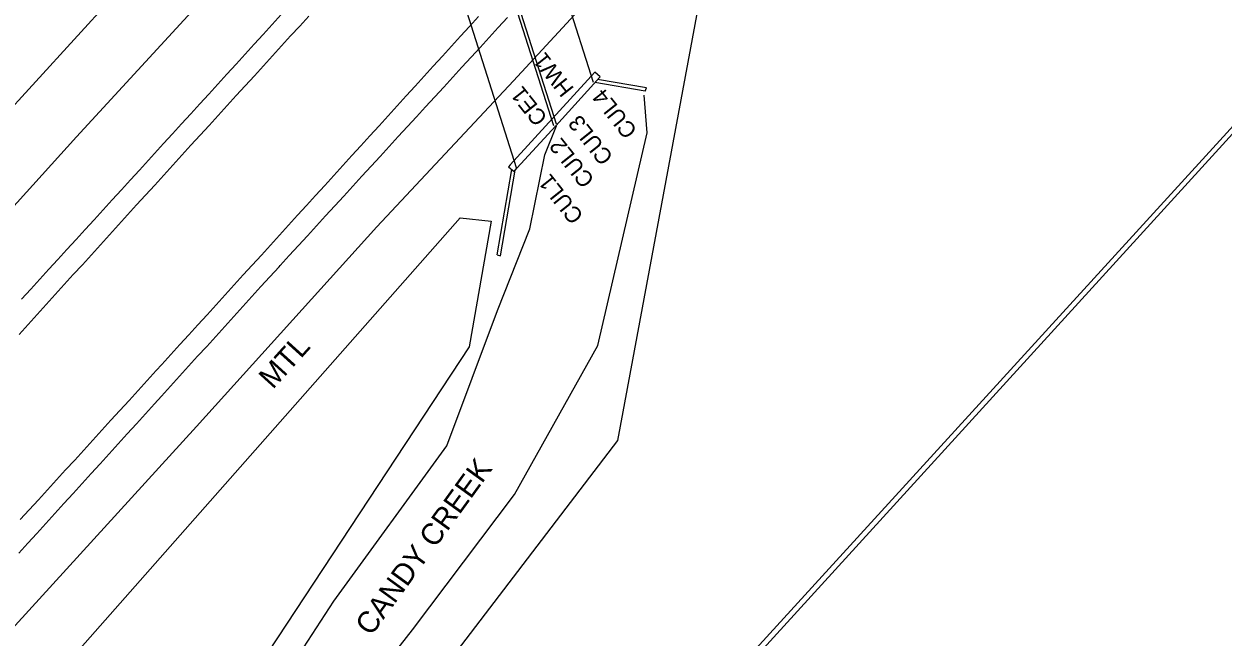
# Model space of a CAD drawing. Extents: x 1806071 to 1809844, y 912722 to 917035.
# Drawn here: x 1808478 to 1808701, y 915262.3 to 915376.2 of the extents above; entities that cross this region are included whole.
import ezdxf

# ---------------------------------------------------------------- set-up
doc = ezdxf.new("R2010")
doc.units = 0
for name, color, linetype in [('Exist Guardrail', 7, 'Continuous'), ('Exist Guardrail Cable Guide Rail', 7, 'Continuous'), ('Exist Guardrail Text', 7, 'Continuous'), ('Exist Horizontal Alignment', 7, 'Continuous'), ('Exist Hydro Stream or Body of Water', 7, 'Continuous'), ('Exist Hydro Stream or Body of Water Text', 7, 'Continuous'), ('Exist Other Culture Fence Line', 7, 'Continuous'), ('Exist Right of Way Line', 7, 'Continuous'), ('Exist Roads EOP', 7, 'Continuous'), ('Exist Roads EOT', 7, 'Continuous'), ('Exist Structure Major Box Culvert or Tunnel Topo', 7, 'Continuous'), ('Exist Structure Major Bridge WW', 7, 'Continuous'), ('Exist Structure Major Deck Tunnel Box Culvert Text', 7, 'Continuous'), ('Exist Structure Minor Head and End Wall', 7, 'Continuous'), ('Exist Vegetation Woods Line', 7, 'Continuous')]:
    doc.layers.add(name, color=color, linetype=linetype)

msp = doc.modelspace()

# ---------------------------------------------------------------- linework, layer by layer
at = {"layer": 'Exist Guardrail'}
msp.add_lwpolyline([(1808591.05, 915389.5), (1808569.06, 915365.7), (1808543.65, 915338.5), (1808510.12, 915301.43), (1808476.4, 915264.39), (1808442.71, 915227.63), (1808412.8, 915194.83), (1808379.91, 915158.29), (1808346.06, 915121.3), (1808316.39, 915089.09), (1808287.07, 915056.31), (1808258.76, 915023.41), (1808230.12, 914989.62), (1808202.58, 914956.19), (1808174.39, 914923.17), (1808146.14, 914889.53), (1808117.77, 914855.87), (1808088.77, 914822.19), (1808060.62, 914790.15), (1808030.71, 914757.47), (1808001.37, 914724.91), (1807974.55, 914694.38)], dxfattribs=at)
at = {"layer": 'Exist Guardrail Cable Guide Rail'}
msp.add_lwpolyline([(1808336.06, 915188.72), (1808363.24, 915218.4), (1808387.13, 915244.72), (1808412.78, 915272.78), (1808437.24, 915299.61), (1808463.92, 915328.91), (1808487.83, 915355.26), (1808513.5, 915383.23), (1808538.93, 915411.52), (1808563.03, 915437.7), (1808575.67, 915451.68), (1808586.31, 915463.32), (1808592.39, 915469.88), (1808616.15, 915495.99), (1808637.91, 915519.85), (1808660.97, 915545.25), (1808684.67, 915571.48), (1808707.85, 915596.81)], dxfattribs=at)
at = {"layer": 'Exist Horizontal Alignment'}
msp.add_line((1806073.69, 912724.84), (1809374.2, 916346.52), dxfattribs=at)
at = {"layer": 'Exist Hydro Stream or Body of Water'}
for points in [[(1808520.56, 915222.15), (1808528.5, 915235.71), (1808550.31, 915263.62), (1808569.28, 915288.78), (1808584.74, 915316.49), (1808593.9, 915355.98), (1808593.37, 915362.99)], [(1808535.69, 915268.92), (1808556.66, 915297.83), (1808566.08, 915322.96), (1808572.13, 915338.17), (1808574.92, 915351.92), (1808577.05, 915357.31)], [(1808507.82, 915230.69), (1808517.93, 915241.7), (1808535.69, 915268.92)]]:
    msp.add_lwpolyline(points, dxfattribs=at)
at = {"layer": 'Exist Other Culture Fence Line'}
msp.add_lwpolyline([(1809083.03, 915774.32), (1808984.81, 915666.52), (1808925.72, 915601.39), (1808852.14, 915520.8), (1808595.36, 915239.5)], dxfattribs=at)
at = {"layer": 'Exist Right of Way Line'}
msp.add_line((1809840.95, 916604.82), (1808525.76, 915161.65), dxfattribs=at)
at = {"layer": 'Exist Roads EOP'}
for points in [[(1808477.08, 915277.85), (1808478.76, 915279.7), (1808480.44, 915281.55), (1808482.12, 915283.4), (1808483.8, 915285.25), (1808485.48, 915287.1), (1808487.17, 915288.95), (1808488.85, 915290.8), (1808490.53, 915292.65), (1808492.21, 915294.5), (1808493.89, 915296.35), (1808495.57, 915298.2), (1808497.25, 915300.05), (1808498.94, 915301.9), (1808500.62, 915303.75), (1808502.3, 915305.6), (1808503.62, 915307.05), (1808505.3, 915308.9), (1808506.98, 915310.76), (1808508.66, 915312.61), (1808510.34, 915314.46), (1808512.02, 915316.31), (1808513.7, 915318.16), (1808515.38, 915320.01), (1808517.06, 915321.86), (1808518.75, 915323.71), (1808520.43, 915325.56), (1808522.11, 915327.41), (1808523.79, 915329.26), (1808525.47, 915331.12), (1808525.68, 915331.35), (1808527.37, 915333.2), (1808529.06, 915335.04), (1808530.75, 915336.88), (1808532.44, 915338.72), (1808534.13, 915340.57), (1808535.82, 915342.41), (1808537.51, 915344.25), (1808539.2, 915346.09), (1808540.89, 915347.94), (1808542.58, 915349.78), (1808544.27, 915351.62), (1808545.96, 915353.46), (1808547.65, 915355.31), (1808549.34, 915357.15), (1808551.03, 915358.99), (1808552.72, 915360.83), (1808554.41, 915362.68), (1808556.1, 915364.52), (1808557.79, 915366.36), (1808559.48, 915368.2), (1808561.17, 915370.05), (1808562.86, 915371.89), (1808564.55, 915373.73), (1808566.24, 915375.57), (1808567.93, 915377.42)], [(1808525.89, 915378), (1808524.21, 915376.16), (1808522.52, 915374.31), (1808520.84, 915372.46), (1808519.15, 915370.61), (1808517.47, 915368.77), (1808515.79, 915366.92), (1808514.1, 915365.07), (1808512.42, 915363.22), (1808510.73, 915361.38), (1808509.05, 915359.53), (1808507.36, 915357.68), (1808505.68, 915355.83), (1808504, 915353.99), (1808502.31, 915352.14), (1808501.22, 915350.94), (1808499.53, 915349.09), (1808497.84, 915347.25), (1808496.16, 915345.4), (1808494.47, 915343.56), (1808492.78, 915341.71), (1808491.1, 915339.86), (1808489.41, 915338.02), (1808487.72, 915336.17), (1808486.04, 915334.33), (1808484.35, 915332.48), (1808482.66, 915330.64), (1808480.98, 915328.79), (1808479.29, 915326.95), (1808477.6, 915325.1)]]:
    msp.add_lwpolyline(points, dxfattribs=at)
at = {"layer": 'Exist Roads EOT'}
for points in [[(1808530.99, 915377.7), (1808529.31, 915375.86), (1808527.62, 915374.01), (1808525.94, 915372.16), (1808524.25, 915370.31), (1808522.57, 915368.47), (1808520.88, 915366.62), (1808519.2, 915364.77), (1808517.51, 915362.93), (1808515.83, 915361.08), (1808514.15, 915359.23), (1808512.46, 915357.38), (1808510.78, 915355.54), (1808509.09, 915353.69), (1808507.41, 915351.84), (1808505.72, 915349.99), (1808504.04, 915348.15), (1808502.35, 915346.3), (1808500.66, 915344.44), (1808498.98, 915342.59), (1808497.3, 915340.74), (1808495.62, 915338.89), (1808493.94, 915337.04), (1808492.26, 915335.19), (1808490.58, 915333.34), (1808488.9, 915331.49), (1808487.22, 915329.64), (1808485.54, 915327.79), (1808483.86, 915325.93), (1808482.18, 915324.08), (1808480.5, 915322.23), (1808478.82, 915320.38), (1808477.14, 915318.53)], [(1808477.35, 915284.1), (1808479.04, 915285.95), (1808480.72, 915287.8), (1808482.41, 915289.64), (1808484.1, 915291.49), (1808485.78, 915293.34), (1808487.47, 915295.18), (1808489.15, 915297.03), (1808490.84, 915298.88), (1808492.52, 915300.72), (1808494.21, 915302.57), (1808495.89, 915304.41), (1808497.58, 915306.26), (1808499.26, 915308.11), (1808500.95, 915309.95), (1808502.63, 915311.8), (1808503.67, 915312.94), (1808505.35, 915314.79), (1808507.04, 915316.63), (1808508.72, 915318.48), (1808510.4, 915320.33), (1808512.09, 915322.18), (1808513.77, 915324.03), (1808515.45, 915325.88), (1808517.13, 915327.73), (1808518.82, 915329.58), (1808520.5, 915331.42), (1808522.18, 915333.27), (1808523.87, 915335.12), (1808525.55, 915336.97), (1808527.23, 915338.82), (1808528.92, 915340.67), (1808530.6, 915342.52), (1808532.28, 915344.37), (1808533.96, 915346.22), (1808535.65, 915348.06), (1808537.33, 915349.91), (1808539.01, 915351.76), (1808540.7, 915353.61), (1808542.38, 915355.46), (1808544.06, 915357.31), (1808545.74, 915359.16), (1808547.43, 915361.01), (1808549.11, 915362.85), (1808550.79, 915364.7), (1808552.48, 915366.55), (1808554.16, 915368.4), (1808555.84, 915370.25), (1808557.52, 915372.1), (1808559.21, 915373.95), (1808560.89, 915375.8), (1808562.57, 915377.64)]]:
    msp.add_lwpolyline(points, dxfattribs=at)
at = {"layer": 'Exist Structure Major Box Culvert or Tunnel Topo'}
for p, q in [((1808583.97, 915365.39), (1808519.67, 915567.57)), ((1808512.7, 915559.72), (1808576.98, 915357.67)), ((1808576.55, 915357.32), (1808512.26, 915559.39)), ((1808505.3, 915551.64), (1808569.58, 915349.53))]:
    msp.add_line(p, q, dxfattribs=at)
at = {"layer": 'Exist Structure Major Bridge WW'}
for p, q in [((1808593.58, 915363.74), (1808593.77, 915364.36)), ((1808566.02, 915333.35), (1808566.65, 915333.13))]:
    msp.add_line(p, q, dxfattribs=at)
at = {"layer": 'Exist Structure Minor Head and End Wall'}
for p, q in [((1808593.77, 915364.36), (1808584.71, 915365.92)), ((1808593.58, 915363.74), (1808584.21, 915365.37)), ((1808566.02, 915333.35), (1808568.74, 915349.17)), ((1808566.65, 915333.13), (1808569.4, 915349.05)), ((1808568.14, 915349.7), (1808569.18, 915348.79))]:
    msp.add_line(p, q, dxfattribs=at)
for points in [[(1808576.91, 915357.33), (1808585.16, 915366.41), (1808584.22, 915367.31), (1808568.47, 915350.04), (1808568.14, 915349.7)], [(1808569.18, 915348.79), (1808569.7, 915349.44), (1808576.91, 915357.33)]]:
    msp.add_lwpolyline(points, dxfattribs=at)
at = {"layer": 'Exist Vegetation Woods Line'}
for points in [[(1808397.76, 915010.37), (1808398.17, 915063.08), (1808401.78, 915078.95), (1808456.47, 915136.33), (1808525.87, 915216.84), (1808588.47, 915298.84), (1808603.34, 915378.8), (1808593.62, 915389.17), (1808703.69, 915510.62), (1809133.9, 915968.11), (1809176.35, 915989.33), (1809248.65, 915971.39)], [(1808108.12, 914683.23), (1808099.27, 914714.87), (1808116.08, 914804.21), (1808120.23, 914842.94), (1808559.12, 915340.21), (1808564.92, 915339.58), (1808560.84, 915316.2), (1808513.2, 915243.98), (1808463.81, 915181.71), (1808444.02, 915172.44), (1808388.95, 915106.15), (1808359.09, 915070.98), (1808353.92, 915054.91), (1808362.94, 915036.53), (1808366.74, 915015.13), (1808346.47, 914993.89), (1808341.37, 914946.67)]]:
    msp.add_lwpolyline(points, dxfattribs=at)

# ---------------------------------------------------------------- texts
at = {"layer": 'Exist Guardrail Text'}
msp.add_text('MTL', height=4, rotation=47.8718, dxfattribs=at).set_placement((1808524.32, 915308.19))
at = {"layer": 'Exist Hydro Stream or Body of Water Text'}
msp.add_text('CANDY CREEK', height=4, rotation=54.0436, dxfattribs=at).set_placement((1808542.59, 915262.29))
at = {"layer": 'Exist Structure Major Deck Tunnel Box Culvert Text'}
for s, p in [('HW1', (1808580.44, 915364.23)), ('CE1', (1808575.54, 915358.81)), ('CUL4', (1808592.22, 915356.45)), ('CUL3', (1808587.76, 915351.54)), ('CUL2', (1808584.27, 915347.3)), ('CUL1', (1808582.24, 915340.58))]:
    msp.add_text(s, height=3, rotation=128.5031, dxfattribs=at).set_placement(p)

doc.saveas('drawing.dxf')
